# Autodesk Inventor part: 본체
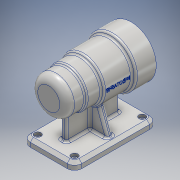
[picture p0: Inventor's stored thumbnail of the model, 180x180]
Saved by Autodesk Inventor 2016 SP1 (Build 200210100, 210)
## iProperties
Created: 2016-06
Part Number: 본체
Material: 알루미늄 6061
Document SubType Name: Modeling
Designer: basic
Density: 2.7 g/cm^3
Appearance: 알루미늄 - 평지
Mass: 671.088 g
Surface Area: 648.112 cm^2
Volume: 248.551 cm^3
Author: basic
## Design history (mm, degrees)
sketch "스케치1"
  geometry: L1 (35, 56)-(-35, 56); L2 (-35, 56)-(-35, -56); L3 (-35, -56)-(35, -56); L4 (35, -56)-(35, 56); L5 (35, 56)-(-35, -56); L6 (-35, 56)-(35, -56); 1 further point
  constraints: 12 end point, 2 midpoint, 2 parallel, 1 horizontal, 1 perpendicular
  dimensions: "d0" = 112 distance of L1.end L2.end; "d1" = 70 distance of L1.start L1.end
extrude "돌출1" new body sketch "스케치1" distance "d2" = 10; taper "d3" = 0 deg
fillet "모깎기1" dims "d4" = 10
sketch "스케치2"
  geometry: L1 (25, 46)-(-25, 46); L2 (-25, 46)-(-25, -46); L3 (-25, -46)-(25, -46); L4 (25, -46)-(25, 46); L5 (25, 46)-(-25, -46); L6 (-25, 46)-(25, -46); 5 further points
  constraints: 12 end point, 4 coincident, 2 midpoint, 2 parallel, 1 horizontal, 1 perpendicular
  dimensions: "d9" = 92 distance of L1.end L2.end; "d10" = 50 distance of L2.end L3.end
hole "구멍1" sketch "스케치2" at (-25, -46), (-25, 46), (25, 46), (25, -46) diameter "d11" = 5; stored, may be unused: countersink angle "d15" = 90 deg, drill point angle "d17" = 118 deg; dims "d12" = 6, "d13" = 9, "d14" = 4, "d16" = 8
chamfer "모따기1" distance "d18" = 4; stored, may be unused: second distance "d19" = 2, angle "d20" = 45 deg
sketch "스케치3"
  geometry: L1 (-56, 70)-(56, 70); L2 (-46, 0)-(46, 0) reference; L3 (-56, 70)-(-56, 95); L4 (-56, 95)-(-31, 95); L5 (-31, 95)-(-31, 97); L6 (-31, 97)-(-11, 97); L7 (-11, 97)-(-11, 100); L8 (-11, 100)-(28, 100); L9 (28, 100)-(28, 104); L10 (28, 104)-(56, 104); L11 (56, 104)-(56, 70); 3 further points
  constraints: 20 end point, 4 perpendicular, 3 parallel, 2 midpoint, 2 vertical, 1 horizontal, 1 vertical alignment
  dimensions: "d21" = 70 distance between parallel lines of L2 L1; "d22" = 112 distance of L1.start L1.end; "d23" = 25 distance of L3.end L4.end; "d24" = 45 distance between parallel lines of L3 L7; "d25" = 84 distance between parallel lines of L3 L9; "d26" = 68 diameter of L10 L1; "d27" = 60 diameter of L8 L1; "d28" = 54 diameter of L6 L1; "d29" = 50 diameter of L4 L1
revolve "회전1" sketch "스케치3" stored, may be unused: angle "d30" = 90 deg
sketch "스케치4"
  geometry: L1 (-56, 45)-(-56, 95) reference; L2 (-56, 70)-(56, 70); L3 (56, 36)-(56, 104) reference; L4 (52, 10)-(56, 6) reference; L5 (56, 6)-(56, 0) reference; L6 (56, 0)-(-56, 0) reference; L7 (-56, 0)-(-56, 6) reference; L8 (-56, 6)-(-52, 10) reference; L9 (-52, 10)-(52, 10) reference; L10 (-56, 45)-(-56, 95) reference; L11 (-56, 95)-(-31, 95) reference; L12 (-31, 95)-(-31, 97) reference; L13 (-31, 97)-(-11, 97) reference; L14 (-11, 97)-(-11, 100) reference; L15 (-11, 100)-(28, 100) reference; L16 (28, 100)-(28, 104) reference; L17 (28, 104)-(56, 104) reference; L18 (56, 104)-(56, 36) reference; L19 (56, 36)-(28, 36) reference; L20 (28, 36)-(28, 40) reference; L21 (28, 40)-(-11, 40) reference; L22 (-11, 40)-(-11, 43) reference; L23 (-11, 43)-(-31, 43) reference; L24 (-31, 43)-(-31, 45) reference; L25 (-31, 45)-(-56, 45) reference; L26 (-50, 70)-(-50, 80.5); L27 (-50, 80.5)-(-47, 80.5); L28 (-47, 80.5)-(-47, 86); L29 (-47, 86)-(-43, 86); L30 (-43, 86)-(-43, 87.5); L31 (-43, 87.5)-(-25, 87.5); L32 (-25, 87.5)-(-25, 91); L33 (-25, 91)-(-13, 91); L34 (-13, 91)-(-13, 94); L35 (-13, 94)-(41, 94); L36 (41, 94)-(41, 91); L37 (41, 91)-(56, 91); L38 (56, 91)-(56, 70); 1 further point
  constraints: 28 end point, 11 perpendicular, 2 midpoint, 2 point on line, 1 collinear, 1 vertical
  dimensions: "d31" = 3 distance of L26.end L27.end; "d32" = 4 distance of L28.end L29.end; "d34" = 21 diameter of L27 L2; "d35" = 32 diameter of L29 L2; "d36" = 35 diameter of L31 L2; "d37" = 42 diameter of L33 L2; "d38" = 48 diameter of L35 L2; "d39" = 42 diameter of L37 L2; "d40" = 15 distance of L36.end L37.end; "d41" = 54 distance of L34.end L35.end; "d42" = 12 distance of L32.end L33.end; "d43" = 18 distance of L30.end L31.end
revolve "회전2" sketch "스케치4" stored, may be unused: angle "d44" = 90 deg
fillet "모깎기2" dims "d45" = 10
sketch "스케치6"
  geometry: L1 (-4, -36)-(4, -36); L2 (4, -36)-(4, 36); L3 (4, 36)-(-4, 36); L4 (-4, 36)-(-4, -36); L5 (4, -36)-(-4, 36); L6 (-25, -56)-(25, -56) reference; 2 further points
  constraints: 10 end point, 2 parallel, 1 coincident, 1 horizontal, 1 midpoint, 1 perpendicular
  dimensions: "d48" = 20 distance between parallel lines of L6 L1; "d49" = 8 distance between parallel lines of L2 L4
extrude "돌출2" join sketch "스케치6" stored distance "d50" = 10; taper "d51" = 0 deg
sketch "스케치7"
  geometry: L1 (-35, 6)-(-31, 10) reference; L2 (-31, 10)-(-4, 10) reference; L3 (-4, 10)-(-4, 40.268) reference; L4 (4, 40.268)-(4, 10) reference; L5 (4, 10)-(31, 10) reference; L6 (31, 10)-(35, 6) reference; L7 (35, 6)-(35, 0) reference; L8 (35, 0)-(-35, 0) reference; L9 (-35, 0)-(-35, 6) reference; L10 (-15.509, 44.32)-(-28, 10); L11 (-25, 10)-(25, 10) reference; C1 r 24 at (0, 70) reference; A1 r 30 centre (0, 70) between (4, 40.268) and (-4, 40.268) reference; 1 further point
  constraints: 2 end point, 1 point on circle, 1 point on line
  dimensions: "d52" = 7 horizontal distance of L8.end L10.end; "d54" = 110 deg angle of L10 L2
feature "리브1" sketch "스케치7" dims "d56" = 1, "d57" = 8, "d58" = 0, "d59" = 0, "d60" = 1, "d61" = 1
sketch "스케치8"
  geometry: L1 (0, 0)-(0, -26); C1 r 25 at (0, 0) reference; 2 further points
  constraints: 2 end point, 1 coincident, 1 vertical
  dimensions: "d62" = 26 distance of L1.start L1.end
hole "구멍2" sketch "스케치8" at (0, -26) diameter "d63" = 3.242; stored, may be unused: countersink angle "d67" = 90 deg, drill point angle "d69" = 118 deg; dims "d64" = 8, "d65" = 9, "d66" = 4, "d68" = 11
fillet "모깎기3" dims "d73" = 3
fillet "모깎기4" dims "d74" = 3
fillet "모깎기6" dims "d76" = 3
fillet "모깎기7" dims "d77" = 3
fillet "모깎기8" dims "d78" = 3
fillet "모깎기10" dims "d82" = 3
chamfer "모따기2" distance "d83" = 1; stored, may be unused: second distance "d84" = 2, angle "d85" = 45 deg
fillet "모깎기12" dims "d87" = 0.3
node "작업 평면2"
sketch "스케치11"
  geometry: L1 (-8.804, 70)-(25, 70) reference; L2 (56, 54)-(30.657, 54) reference; L3 (56, 86)-(56, 54) reference; L4 (30.657, 86)-(56, 86) reference; L5 (54.66, 0)-(-54.66, 0) reference; L6 (-54.66, 0)-(-54.66, 6) reference; L7 (-49.317, 10)-(-2.061, 10) reference; L8 (-1, 10.002)-(1, 10.002) reference; L9 (2.061, 10)-(49.317, 10) reference; L10 (54.66, 6)-(54.66, 0) reference; L11 (56, 36)-(56, 104) reference; 5 further points
  constraints: 1 horizontal alignment, 1 midpoint, 9 other
  dimensions: "d89" = 48 distance from line of L11 point (8, 70)
feature "엠보싱1" sketch "스케치11" dims "d0" = 112, "d1" = 70, "d11" = 5, "d13" = 9, "d14" = 4, "d16" = 8, "d90" = 0.5, "d91" = 0
fillet "모깎기13" dims "d92" = 3
node "솔리드1"
mirror "대칭1"
pattern_circular "원형 패턴1" dims angle "d71" = 360 deg
node "절단 모서리 투영1"
node "절단 모서리 투영3"
node "절단 모서리 투영5"
